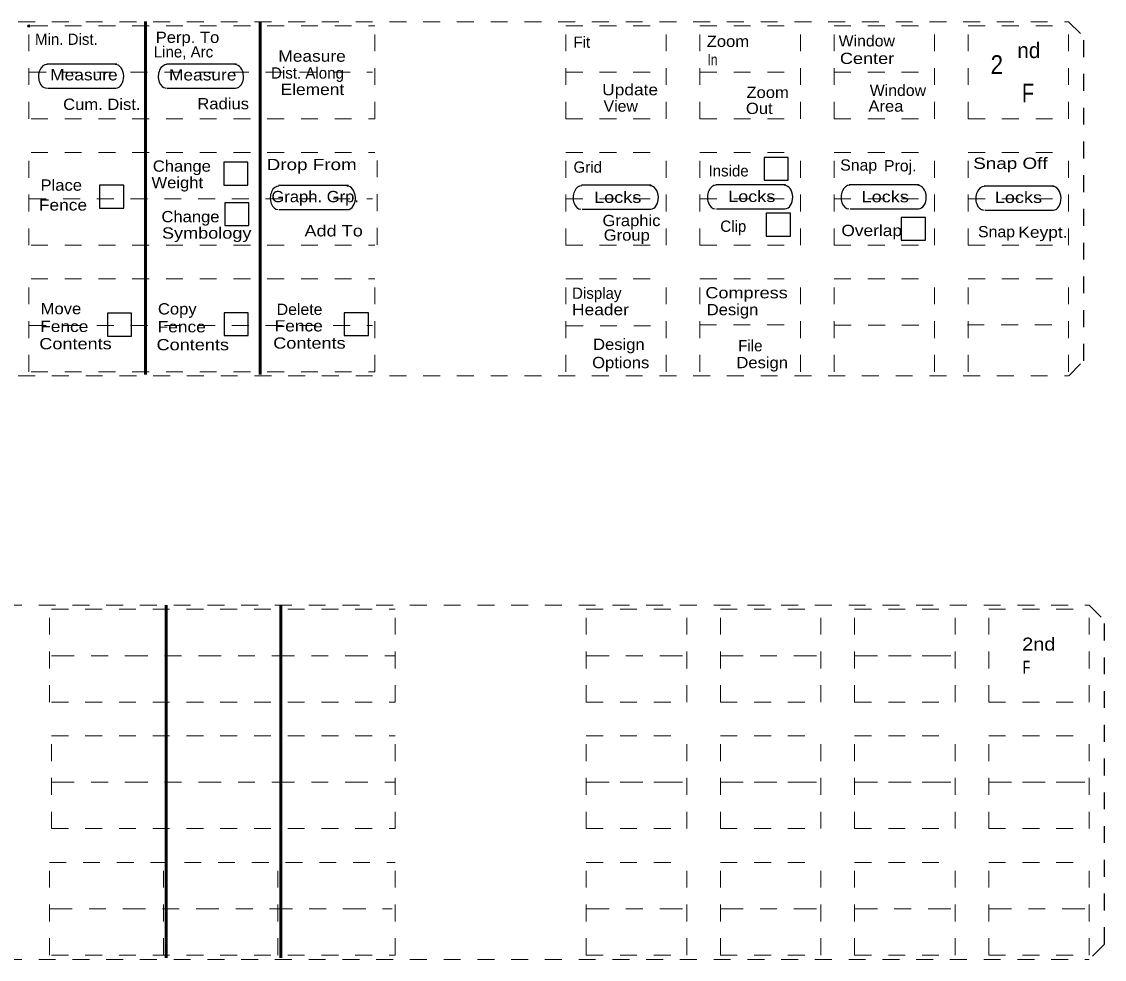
# Model space of a CAD drawing. Extents: x 139.3 to 176, y 56 to 66.7.
# Drawn here: x 169.57 to 175.99, y 57.79 to 63.34 of the extents above; entities that cross this region are included whole.
import ezdxf

# ---------------------------------------------------------------- set-up
doc = ezdxf.new("R2010")
doc.units = 0
doc.header["$LTSCALE"] = 0.027
doc.header["$PDMODE"] = 32
doc.header["$PDSIZE"] = 0.0135
for name, pattern in [('DOT_DASHED', [7.7, 5, -1.2, 0.3, -1.2]), ('DOTTED', [1.5, 0.3, -1.2]), ('MEDIUM_DASHED', [4.5, 3, -1.5]), ('SHORT_DASHED', [2.7, 1.5, -1.2])]:
    doc.linetypes.add(name, pattern=pattern)
for name, color, linetype, lineweight in [('1', 7, 'DOTTED', 13), ('2', 7, 'DOTTED', 13), ('3', 7, 'DOT_DASHED', 13), ('5', 7, 'Continuous', 25)]:
    doc.layers.add(name, color=color, linetype=linetype, lineweight=lineweight)

msp = doc.modelspace()

# ---------------------------------------------------------------- linework, layer by layer
at = {"layer": '1', "linetype": 'MEDIUM_DASHED'}
for p, q in [((162.35208, 63.3431), (175.77689, 63.3431)), ((162.35208, 61.2431), (175.77689, 61.2431)), ((162.4736, 59.88515), (175.89841, 59.88515)), ((162.4736, 57.78515), (175.89841, 57.78515))]:
    msp.add_line(p, q, dxfattribs=at)
at = {"layer": '1', "linetype": 'Continuous', "lineweight": 53}
for p, q in [((170.30688, 63.3434), (170.30688, 61.25284)), ((170.98588, 63.3434), (170.98588, 61.25284)), ((170.4284, 59.88545), (170.4284, 57.79489)), ((171.1074, 59.88545), (171.1074, 57.79489))]:
    msp.add_line(p, q, dxfattribs=at)
at = {"layer": '1', "linetype": 'MEDIUM_DASHED', "lineweight": 25}
for p, q in [((175.77689, 63.3431), (175.86689, 63.2531)), ((175.86689, 61.3331), (175.86689, 63.2531)), ((175.777, 61.24351), (175.86394, 61.33045)), ((175.89841, 59.88515), (175.98841, 59.79515)), ((175.98841, 57.87515), (175.98841, 59.79515)), ((175.98841, 57.87515), (175.89841, 57.78515))]:
    msp.add_line(p, q, dxfattribs=at)
at = {"layer": '2'}
for p, q in [((169.61489, 62.7681), (169.61489, 63.3181)), ((169.62789, 63.3181), (171.66489, 63.3181)), ((171.66489, 62.7681), (171.66489, 63.3181)), ((172.79689, 62.7681), (172.79689, 63.3181)), ((172.79689, 63.3181), (173.39189, 63.3181)), ((173.39189, 62.7681), (173.39189, 63.3181)), ((173.59189, 62.7681), (173.59189, 63.3181)), ((173.59189, 63.3181), (174.18689, 63.3181)), ((174.18689, 62.7681), (174.18689, 63.3181)), ((174.38689, 62.7681), (174.38689, 63.3181)), ((174.38689, 63.3181), (174.98189, 63.3181)), ((174.98189, 62.7681), (174.98189, 63.3181)), ((175.18189, 62.7681), (175.18189, 63.3181)), ((175.18189, 63.3181), (175.77689, 63.3181)), ((175.77689, 62.7681), (175.77689, 63.3181)), ((169.61829, 63.0431), (171.65049, 63.0431)), ((172.79689, 63.0431), (173.39189, 63.0431)), ((173.59189, 63.0431), (174.18689, 63.0431)), ((174.38689, 63.0431), (174.98189, 63.0431)), ((169.62789, 62.7681), (171.66489, 62.7681)), ((172.79689, 62.7681), (173.39189, 62.7681)), ((173.59189, 62.7681), (174.18689, 62.7681)), ((174.38689, 62.7681), (174.98189, 62.7681)), ((175.18189, 62.7681), (175.77689, 62.7681)), ((169.61489, 62.0181), (169.61489, 62.5681)), ((169.62789, 62.5681), (171.66489, 62.5681)), ((171.67847, 62.02096), (171.67847, 62.57096)), ((172.79689, 62.0181), (172.79689, 62.5681)), ((172.79689, 62.5681), (173.39189, 62.5681)), ((173.39189, 62.0181), (173.39189, 62.5681)), ((173.59189, 62.0181), (173.59189, 62.5681)), ((173.59189, 62.5681), (174.18689, 62.5681)), ((174.18689, 62.0181), (174.18689, 62.5681)), ((174.38689, 62.0181), (174.38689, 62.5681)), ((174.38689, 62.5681), (174.98189, 62.5681)), ((174.98189, 62.0181), (174.98189, 62.5681)), ((175.18189, 62.0181), (175.18189, 62.5681)), ((175.18189, 62.5681), (175.77689, 62.5681)), ((175.77689, 62.0181), (175.77689, 62.5681)), ((169.61829, 62.2931), (171.65049, 62.2931)), ((172.79689, 62.2931), (173.39189, 62.2931)), ((173.59189, 62.2931), (174.18689, 62.2931)), ((174.38689, 62.2931), (174.98189, 62.2931)), ((175.18189, 62.2931), (175.77689, 62.2931)), ((169.62789, 62.0181), (171.66489, 62.0181)), ((172.79689, 62.0181), (173.39189, 62.0181)), ((173.59189, 62.0181), (174.18689, 62.0181)), ((174.38689, 62.0181), (174.98189, 62.0181)), ((175.18189, 62.0181), (175.77689, 62.0181)), ((169.61489, 61.2681), (169.61489, 61.8181)), ((169.62789, 61.8181), (171.66489, 61.8181)), ((171.66489, 61.2681), (171.66489, 61.8181)), ((172.79689, 61.2681), (172.79689, 61.8181)), ((172.79689, 61.8181), (173.39189, 61.8181)), ((173.39189, 61.2681), (173.39189, 61.8181)), ((173.59189, 61.2681), (173.59189, 61.8181)), ((173.59189, 61.8181), (174.18689, 61.8181)), ((174.18689, 61.2681), (174.18689, 61.8181)), ((174.38689, 61.2681), (174.38689, 61.8181)), ((174.38689, 61.8181), (174.98189, 61.8181)), ((174.98189, 61.2681), (174.98189, 61.8181)), ((175.18189, 61.2681), (175.18189, 61.8181)), ((175.18189, 61.8181), (175.77689, 61.8181)), ((175.77689, 61.2681), (175.77689, 61.8181)), ((169.61829, 61.5431), (171.65049, 61.5431)), ((172.79961, 61.54068), (173.39461, 61.54068)), ((173.59021, 61.54611), (174.18521, 61.54611)), ((174.38897, 61.54339), (174.98397, 61.54339)), ((175.17686, 61.54611), (175.77186, 61.54611)), ((169.62789, 61.2681), (171.66489, 61.2681)), ((169.73641, 59.31015), (169.73641, 59.86015)), ((169.74941, 59.86015), (171.78641, 59.86015)), ((170.42681, 59.31015), (170.42681, 59.86015)), ((171.10421, 59.31015), (171.10421, 59.86015)), ((171.78641, 59.31015), (171.78641, 59.86015)), ((172.91841, 59.31015), (172.91841, 59.86015)), ((172.91841, 59.86015), (173.51341, 59.86015)), ((173.51341, 59.31015), (173.51341, 59.86015)), ((173.71341, 59.31015), (173.71341, 59.86015)), ((173.71341, 59.86015), (174.30841, 59.86015)), ((174.30841, 59.31015), (174.30841, 59.86015)), ((174.50841, 59.31015), (174.50841, 59.86015)), ((174.50841, 59.86015), (175.10341, 59.86015)), ((175.10341, 59.31015), (175.10341, 59.86015)), ((175.30341, 59.31015), (175.30341, 59.86015)), ((175.30341, 59.86015), (175.89841, 59.86015)), ((175.89841, 59.31015), (175.89841, 59.86015)), ((169.74941, 59.31015), (171.78641, 59.31015)), ((172.91841, 59.31015), (173.51341, 59.31015)), ((173.71341, 59.31015), (174.30841, 59.31015)), ((174.50841, 59.31015), (175.10341, 59.31015)), ((175.30341, 59.31015), (175.89841, 59.31015)), ((169.74941, 59.11015), (171.78641, 59.11015)), ((169.74941, 58.56015), (169.74941, 59.11015)), ((170.42681, 58.56015), (170.42681, 59.11015)), ((171.10421, 58.56015), (171.10421, 59.11015)), ((171.78641, 58.56015), (171.78641, 59.11015)), ((172.91841, 58.56015), (172.91841, 59.11015)), ((172.91841, 59.11015), (173.51341, 59.11015)), ((173.51341, 58.56015), (173.51341, 59.11015)), ((173.71341, 58.56015), (173.71341, 59.11015)), ((173.71341, 59.11015), (174.30841, 59.11015)), ((174.30841, 58.56015), (174.30841, 59.11015)), ((174.50841, 58.56015), (174.50841, 59.11015)), ((174.50841, 59.11015), (175.10341, 59.11015)), ((175.10341, 58.56015), (175.10341, 59.11015)), ((175.30341, 58.56015), (175.30341, 59.11015)), ((175.30341, 59.11015), (175.89841, 59.11015)), ((175.89841, 58.56015), (175.89841, 59.11015)), ((169.74941, 58.56015), (171.78641, 58.56015)), ((172.91841, 58.56015), (173.51341, 58.56015)), ((173.71341, 58.56015), (174.30841, 58.56015)), ((174.50841, 58.56015), (175.10341, 58.56015)), ((175.30341, 58.56015), (175.89841, 58.56015)), ((169.73641, 58.36015), (171.78641, 58.36015)), ((169.73641, 57.81015), (169.73641, 58.36015)), ((170.41381, 57.81015), (170.41381, 58.36015)), ((171.09121, 57.81015), (171.09121, 58.36015)), ((171.78641, 57.81015), (171.78641, 58.36015)), ((172.91841, 57.81015), (172.91841, 58.36015)), ((172.91841, 58.36015), (173.51341, 58.36015)), ((173.51341, 57.81015), (173.51341, 58.36015)), ((173.71341, 57.81015), (173.71341, 58.36015)), ((173.71341, 58.36015), (174.30841, 58.36015)), ((174.30841, 57.81015), (174.30841, 58.36015)), ((174.50841, 57.81015), (174.50841, 58.36015)), ((174.50841, 58.36015), (175.10341, 58.36015)), ((175.10341, 57.81015), (175.10341, 58.36015)), ((175.30341, 57.81015), (175.30341, 58.36015)), ((175.30341, 58.36015), (175.89841, 58.36015)), ((175.89841, 57.81015), (175.89841, 58.36015)), ((169.74941, 57.81015), (171.78641, 57.81015)), ((172.91841, 57.81015), (173.51341, 57.81015)), ((173.71341, 57.81015), (174.30841, 57.81015)), ((174.50841, 57.81015), (175.10341, 57.81015)), ((175.30341, 57.81015), (175.89841, 57.81015))]:
    msp.add_line(p, q, dxfattribs=at)
at = {"layer": '3'}
for p, q in [((169.74941, 59.58515), (171.78161, 59.58515)), ((172.91841, 59.58515), (173.51341, 59.58515)), ((173.71341, 59.58515), (174.30841, 59.58515)), ((174.50841, 59.58515), (175.10341, 59.58515)), ((169.74941, 58.83515), (171.78161, 58.83515)), ((172.91841, 58.83515), (173.51341, 58.83515)), ((173.71341, 58.83515), (174.30841, 58.83515)), ((174.50841, 58.83515), (175.10341, 58.83515)), ((175.30341, 58.83515), (175.89841, 58.83515)), ((169.73641, 58.08515), (171.76861, 58.08515)), ((172.91841, 58.08515), (173.51341, 58.08515)), ((173.71341, 58.08515), (174.30841, 58.08515)), ((174.50841, 58.08515), (175.10341, 58.08515)), ((175.30341, 58.08515), (175.89841, 58.08515))]:
    msp.add_line(p, q, dxfattribs=at)
at = {"layer": '3', "linetype": 'SHORT_DASHED'}
for p, q in [((174.50841, 59.58515), (175.10341, 59.58515)), ((172.91841, 58.83515), (173.51341, 58.83515)), ((173.71341, 58.83515), (174.30841, 58.83515)), ((174.50841, 58.83515), (175.10341, 58.83515)), ((175.30341, 58.83515), (175.89841, 58.83515))]:
    msp.add_line(p, q, dxfattribs=at)
at = {"layer": '5'}
for p, q in [((169.72098, 63.09398), (170.13536, 63.09398)), ((170.4307, 63.09362), (170.84508, 63.09362)), ((169.72561, 62.94964), (170.13071, 62.94964)), ((170.43533, 62.94928), (170.84043, 62.94928)), ((171.09421, 62.37336), (171.50859, 62.37336)), ((172.88917, 62.37569), (173.30355, 62.37569)), ((173.68538, 62.37802), (174.09976, 62.37802)), ((174.47693, 62.37803), (174.89131, 62.37803)), ((175.27547, 62.37104), (175.68985, 62.37104)), ((171.09884, 62.22902), (171.50394, 62.22902)), ((172.8938, 62.23135), (173.2989, 62.23135)), ((173.69001, 62.23368), (174.09511, 62.23368)), ((174.48156, 62.23369), (174.88666, 62.23369)), ((175.2801, 62.2267), (175.6852, 62.2267))]:
    msp.add_line(p, q, dxfattribs=at)
for points in [[(170.76948, 62.51033), (170.76948, 62.37508), (170.91285, 62.37508), (170.91285, 62.51033)], [(173.97155, 62.53907), (173.97155, 62.40382), (174.11492, 62.40382), (174.11492, 62.53907)], [(170.03347, 62.37363), (170.03347, 62.23838), (170.17684, 62.23838), (170.17684, 62.37363)], [(170.77595, 62.26971), (170.77595, 62.13446), (170.91932, 62.13446), (170.91932, 62.26971)], [(173.98499, 62.20804), (173.98499, 62.07279), (174.12836, 62.07279), (174.12836, 62.20804)], [(174.78471, 62.18242), (174.78471, 62.04717), (174.92808, 62.04717), (174.92808, 62.18242)], [(170.08004, 61.61467), (170.08004, 61.47942), (170.22341, 61.47942), (170.22341, 61.61467)], [(170.77216, 61.61737), (170.77216, 61.48212), (170.91553, 61.48212), (170.91553, 61.61737)], [(171.48393, 61.61775), (171.48393, 61.4825), (171.6273, 61.4825), (171.6273, 61.61775)]]:
    msp.add_lwpolyline(points, close=True, dxfattribs=at)
for centre, major_axis, start_param, end_param in [((169.72098, 63.01952), (0.00232, 0.06985), 6.2831853, 9.424778), ((170.12839, 63.01952), (-0.00232, 0.06985), 3.1415927, 6.2831853), ((170.43069, 63.01916), (0.00232, 0.06985), 6.2831853, 9.424778), ((170.83811, 63.01916), (-0.00232, 0.06985), 3.1415927, 6.2831853), ((171.09421, 62.2989), (0.00232, 0.06985), 6.2831853, 9.424778), ((171.50163, 62.2989), (-0.00232, 0.06985), 3.1415927, 6.2831853), ((172.88917, 62.30123), (0.00232, 0.06985), 6.2831853, 9.424778), ((173.29659, 62.30123), (-0.00232, 0.06985), 3.1415927, 6.2831853), ((173.68538, 62.30356), (0.00232, 0.06985), 6.2831853, 9.424778), ((174.0928, 62.30356), (-0.00232, 0.06985), 3.1415927, 6.2831853), ((174.47692, 62.30357), (0.00232, 0.06985), 6.2831853, 9.424778), ((174.88434, 62.30357), (-0.00232, 0.06985), 3.1415927, 6.2831853), ((175.27546, 62.29659), (0.00232, 0.06985), 6.2831853, 9.424778), ((175.68288, 62.29659), (-0.00232, 0.06985), 3.1415927, 6.2831853)]:
    msp.add_ellipse(centre, major_axis=major_axis, ratio=0.699144, start_param=start_param, end_param=end_param, dxfattribs=at)
msp.add_point((169.61489, 63.3181), dxfattribs=at)

# ---------------------------------------------------------------- texts
at = {"layer": '1'}
for s, width, p in [('2nd', 1.15, (175.50127, 59.61557)), ('F', 0.7, (175.50501, 59.47818))]:
    msp.add_text(s, height=0.0768, dxfattribs=dict(at, width=width)).set_placement(p)
at = {"layer": '5'}
for s, height, p in [('Min. Dist.', 0.0668, (169.65116, 63.2058)), ('Line, Arc', 0.0668, (170.355, 63.13116)), ('Fit', 0.0668, (172.84216, 63.18827)), ('nd', 0.09216, (175.47234, 63.12719)), ('Dist. Along', 0.0668, (171.05005, 63.00567)), ('Grid', 0.0668, (172.8426, 62.44788)), ('Inside', 0.0668, (173.64235, 62.42577)), ('Clip', 0.0668, (173.71246, 62.09751)), ('Display', 0.0668, (172.83404, 61.70048)), ('File', 0.0668, (173.81868, 61.3894))]:
    msp.add_text(s, height=height, dxfattribs=at).set_placement(p)
for s, height, width, p in [('Perp. To', 0.0668, 1.1, (170.36664, 63.2173)), ('Window', 0.0668, 1.05, (174.4138, 63.19638)), ('Zoom', 0.0668, 1.1, (173.63203, 63.19367)), ('Measure', 0.0668, 1.15, (171.09333, 63.10576)), ('In', 0.0668, 0.8, (173.63651, 63.08471)), ('Center', 0.0668, 1.2, (174.42133, 63.09246)), ('2', 0.1106, 0.9, (175.31417, 63.0338)), ('Measure', 0.0668, 1.15, (169.74156, 62.99517)), ('Measure', 0.0668, 1.15, (170.44536, 62.99478)), ('Element', 0.0668, 1.15, (171.10685, 62.90828)), ('Update', 0.0668, 1.15, (173.01257, 62.90694)), ('Zoom', 0.0668, 1.1, (173.86737, 62.89072)), ('Window', 0.0668, 1.05, (174.59824, 62.9031)), ('F', 0.1106, 0.8, (175.50028, 62.86604)), ('Cum. Dist.', 0.0668, 1.1, (169.81811, 62.82028)), ('Radius', 0.0668, 1.1, (170.61343, 62.82385)), ('View', 0.0668, 1.05, (173.02069, 62.80956)), ('Out', 0.0668, 1.1, (173.86447, 62.79597)), ('Area', 0.0668, 1.1, (174.59029, 62.80958)), ('Change', 0.0668, 1.1, (170.34952, 62.45401)), ('Drop From', 0.0668, 1.25, (171.02435, 62.46331)), ('Snap', 0.0668, 1.05, (174.42311, 62.46018)), ('Proj.', 0.0668, 1.05, (174.68261, 62.45591)), ('Snap Off', 0.0668, 1.25, (175.21141, 62.47062)), ('Place', 0.0668, 1.1, (169.68406, 62.34119)), ('Weight', 0.0668, 1.1, (170.34179, 62.35632)), ('Graph. Grp.', 0.0668, 1.1, (171.0523, 62.27318)), ('Locks', 0.0668, 1.2, (172.96471, 62.26934)), ('Locks', 0.0668, 1.2, (173.75877, 62.27428)), ('Locks', 0.0668, 1.2, (174.54995, 62.27272)), ('Locks', 0.0668, 1.2, (175.33928, 62.2687)), ('Fence', 0.0668, 1.15, (169.67438, 62.22367)), ('Change', 0.0668, 1.1, (170.40067, 62.15436)), ('Graphic', 0.0668, 1.1, (173.01417, 62.13125)), ('Symbology', 0.0668, 1.2, (170.40376, 62.05713)), ('Add To', 0.0668, 1.2, (171.24834, 62.07038)), ('Group', 0.0668, 1.1, (173.02178, 62.04513)), ('Overlap', 0.0668, 1.15, (174.42994, 62.07226)), ('Snap', 0.0668, 1.05, (175.23993, 62.06534)), ('Keypt.', 0.0668, 1.15, (175.47897, 62.06222)), ('Compress', 0.0668, 1.2, (173.62391, 61.70318)), ('Move', 0.0668, 1.1, (169.68511, 61.60911)), ('Copy', 0.0668, 1.1, (170.37993, 61.60752)), ('Delete', 0.0668, 1.05, (171.08382, 61.60483)), ('Header', 0.0668, 1.15, (172.83404, 61.60309)), ('Design', 0.0668, 1.1, (173.63204, 61.6031)), ('Fence', 0.0668, 1.15, (169.68209, 61.50397)), ('Fence', 0.0668, 1.15, (170.37805, 61.50165)), ('Fence', 0.0668, 1.15, (171.07137, 61.50706)), ('Contents', 0.0668, 1.2, (169.67694, 61.40119)), ('Contents', 0.0668, 1.2, (171.06314, 61.40503)), ('Design', 0.0668, 1.1, (172.95847, 61.39751)), ('Contents', 0.0668, 1.2, (170.37177, 61.39533)), ('Options', 0.0668, 1.1, (172.95306, 61.28931)), ('Design', 0.0668, 1.1, (173.80786, 61.28931))]:
    msp.add_text(s, height=height, dxfattribs=dict(at, width=width)).set_placement(p)

doc.saveas('drawing.dxf')
